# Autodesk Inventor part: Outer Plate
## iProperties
Created: 2009-05
Part Number: Outer Plate
Document SubType Name: Modeling
Designer: Sham
Density: 1 g/cm^3
Author: Sham
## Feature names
1. Extrusion1
